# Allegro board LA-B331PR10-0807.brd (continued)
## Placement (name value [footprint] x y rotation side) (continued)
PQ52  -  [DMN65D8LW-7_SOT323-3]  266.36 19.08 0 bottom
PQ53  -  [DMN65D8LW-7_SOT323-3]  292.33 19.4 180 bottom
PQ54  -  [DMN65D8LW-7_SOT323-3]  288.76 17.35 0 bottom
PQ60  -  [DMN65D8LW-7_SOT323-3]  298.27 43.5 270 bottom
PQ61  -  [DMN65D8LW-7_SOT323-3]  298.66 39.02 180 bottom
PQ62  -  [DMN65D8LW-7_SOT323-3]  298.27 33.4 270 bottom
PQ101  FDV301N_G_NL_SOT23-3  [FDV301N_NL_SOT23-3]  298.16 12.12 90 bottom
PQ102  -  [MMST3904-7-F_SOT323-3]  300.97 18.2 270 bottom
PQ300  -  [CSD87330Q3D_SON8-7]  282.91 21.8 90 bottom
PQ501  -  [CSD87330Q3D_SON8-7]  277.61 22.59 270 bottom
PQ503  -  [AON7934_DFN3X3A8-10]  182.66 29.99 0 bottom
PQ600  -  [AON7934_DFN3X3A8-10]  215.98 19 0 bottom
PQ700  -  [CSD87312Q3E_SON8-4]  254.72 21.46 90 bottom
PQ701  -  [DCX124EK-7-F_SC74R-6]  250.77 22.75 270 bottom
PQ702  -  [CSD87351Q5D_SON8-7]  263.03 27.78 180 bottom
PQ703  -  [AON7405_DFN8-5]  258.05 46.64 270 bottom
PQ709  -  [DMN65D8LW-7_SOT323-3]  241.62 24.96 270 bottom
PQ720  -  [SI2303CDS-T1-GE3_SOT23-3]  245.51 22.42 0 bottom
PQ721  -  [DMN65D8LW-7_SOT323-3]  245.1 25.96 270 bottom
PQ900  -  [DMN66D0LDW-7_SOT363-6]  272.9 14.68 90 bottom
PQ901  -  [DMN66D0LDW-7_SOT363-6]  236.6 27.97 0 bottom
PR1  100_0402_1%  [R_0402]  242.15 40.99 0 bottom
PR2  100_0402_1%  [R_0402]  242.15 39.97 0 bottom
PR3  100K_0402_5%  [R_0402]  244.18 38.07 0 bottom
PR5  100_0402_1%  [R_0402]  244.18 38.96 0 bottom
PR7  402K_0402_1%  [R_0402]  246.24 41.85 90 bottom
PR8  324K_0402_1%  [R_0402]  249.29 42.77 270 bottom
PR9  324K_0402_1%  [R_0402]  242.15 41.9 0 bottom
PR10  240K_0402_5%  [R_0402]  244.21 42.77 270 bottom
PR12  402K_0402_1%  [R_0402]  274.5 18.08 90 bottom
PR13  100K_0402_5%  [R_0402]  242.3 27.78 180 bottom
PR30  100K_0402_5%  [R_0402]  239.69 23.87 270 bottom
PR40  100K_0402_5%  [R_0402]  240.26 41.91 180 bottom
PR41  9.1K_0402_1%  [R_0402]  240.27 42.82 180 bottom
PR42  100K_0402_1%  [R_0402]  236.64 33.19 180 bottom
PR43  0_0402_5%  [R_0402]  254.16 40.92 90 bottom
PR44  20K_0402_1%  [R_0402]  255.14 40.92 90 bottom
PR45  20K_0402_1%  [R_0402]  255.03 42.84 180 bottom
PR46  0_0402_5%  [R_0402]  225.78 33.8 180 bottom
PR48  0_0402_5%  [R0402_0OHM]  294.52 20.23 180 bottom
PR49  0_0402_5%  [R_0402]  254.14 39.86 0 bottom
PR55  0_0402_5%  [R_0402]  240.59 23.88 270 bottom
PR56  0_0402_5%  [R0402_0OHM]  239.69 21.2 90 bottom
PR58  100K_0402_5%  [R_0402]  250.26 41.88 90 bottom
PR59  0_0402_5%  [R0402_0OHM]  230.8 32.66 180 bottom
PR60  20K_0402_1%  [R_0402]  294.3 16.22 180 bottom
PR61  1M_0402_5%  [R_0402]  289.41 15.21 90 bottom
PR62  0_0402_5%  [R_0402]  268.06 19.52 0 bottom
PR63  1M_0402_5%  [R_0402]  268.59 18.51 180 bottom
PR65  1M_0402_5%  [R_0402]  288.34 15.27 90 bottom
PR67  0_0402_5%  [R_0402]  230.81 33.54 180 bottom
PR70  100K_0402_5%  [R_0402]  297.9 41.32 270 bottom
PR71  100K_0402_5%  [R_0402]  299.17 40.4 90 bottom
PR72  330K_0402_1%  [R_0402]  299.04 31.45 270 bottom
PR73  249K_0402_1%  [R_0402]  297.86 21.35 90 bottom
PR74  100K_0402_5%  [R_0402]  297.66 35.7 270 bottom
PR75  100K_0402_1%  [R_0402]  300.18 30.53 90 bottom
PR76  210K_0402_1%  [R_0402]  298.81 22.26 270 bottom
PR77  0_0402_5%  [R_0402]  248.14 40.42 180 bottom
PR78  0_0402_5%  [R0402_0OHM]  300.44 41.32 270 bottom
PR79  0_0402_5%  [R0402_0OHM]  294.42 18.45 90 bottom
PR80  560K_0402_1%  [R_0402]  299.22 29.4 180 bottom
PR81  100K_0402_5%  [R_0402]  298.89 35.73 0 bottom
PR93  0_0402_5%  [R0402_0OHM]  268.97 20.41 180 bottom
PR94  1M_0402_5%  [R_0402]  241.77 33.88 0 bottom
PR95  0_0402_5%  [R0402_0OHM]  273.62 18.08 90 bottom
PR102  2.2K_0402_5%  [R_0402]  299.07 16.01 0 bottom
PR103  33_0402_5%  [R_0402]  299.41 14.72 0 bottom
PR104  10K_0402_1%  [R_0402]  300.48 19.96 180 bottom
PR105  100K_0402_1%  [R_0402]  297.88 16.03 90 bottom
PR106  15K_0402_1%  [R_0402]  297.88 17.9 90 bottom
PR130  0_0402_5%  [R_0402]  297.55 14.72 0 bottom
PR300  66.5K_0402_1%  [R_0402]  282.43 34.13 180 bottom
PR301  154K_0402_1%  [R_0402]  279.39 34.13 180 bottom
PR302  100K_0402_1%  [R_0402]  282.43 33.24 180 bottom
PR303  100K_0402_1%  [R_0402]  279.37 33.2 180 bottom
PR304  7.68K_0402_1%  [R_0402]  283.37 34.14 270 bottom
PR305  5.49K_0402_1%  [R_0402]  277.56 34.1 270 bottom
PR306  200_0402_1%  [R_0402]  277.1 31.08 180 bottom
PR307  0_0603_5%  [R_0603]  285.53 29.62 180 bottom
PR308  0_0603_5%  [R_0603]  276.9 28.99 180 bottom
PR309  4.7_0805_5%  [R_0805]  284.77 25.34 90 bottom
PR310  4.7_0805_5%  [R_0805]  276.01 24.77 90 bottom
PR311  100K_0402_1%  [R_0402]  281.16 35.91 180 bottom
PR330  0_0402_5%  [R0402_0OHM]  284.31 33.11 0 bottom
PR331  0_0402_5%  [R0402_0OHM]  277.1 32.1 180 bottom
PR400  0_0402_5%  [R0402_0OHM]  286.45 45.22 0 bottom
PR401  88.7K_0402_1%  [R_0402]  283.95 41.6 0 bottom
PR402  4.7_0805_5%  [R_0805]  291.04 38.9 0 bottom
PR403  100K_0402_1%  [R_0402]  283.93 42.54 0 bottom
PR404  100K_0402_5%  [R_0402]  285.75 39.39 180 bottom
PR405  0_0402_5%  [R0402_0OHM]  274.26 45.48 0 bottom
PR406  412K_0402_1%  [R_0402]  271.61 41.75 0 bottom
PR407  4.7_0805_5%  [R_0805]  278.84 39.15 0 bottom
PR408  324K_0402_1%  [R_0402]  271.61 42.77 0 bottom
PR409  100K_0402_5%  [R_0402]  273.55 39.64 180 bottom
PR500  0_0402_5%  [R0402_0OHM]  73.26 29.66 180 bottom
PR501  1M_0402_1%  [R_0402]  73.26 28.78 180 bottom
PR502  4.7_1206_5%  [R_1206]  81.88 29.47 270 bottom
PR503  0_0603_5%  [R_0603]  74.39 20.65 180 bottom
PR504  0_0402_5%  [R_0402]  72.34 25.6 0 bottom
PR505  21K_0402_1%  [R_0402]  72.68 23.87 270 bottom
PR506  100K_0402_5%  [R_0402]  72.34 27 0 bottom
PR507  0_0402_5%  [R0402_0OHM]  73.26 24.71 180 bottom
PR508  35.7K_0402_1%  [R_0402]  71.66 22.85 90 bottom
PR509  75_0402_1%  [R_0402]  193.28 16.86 180 bottom
PR510  130_0402_1%  [R_0402]  190.33 18.89 0 bottom
PR511  0_0402_5%  [R0402_0OHM]  187.49 15.28 270 bottom
PR512  1.91K_0402_1%  [R_0402]  190.16 15.28 270 bottom
PR513  54.9_0402_1%  [R_0402]  190.33 17.01 0 bottom
PR514  73.2K_0402_1%  [R_0402]  190.33 20.16 0 bottom
PR515  0_0402_5%  [R0402_0OHM]  193.28 18.89 180 bottom
PR516  0_0402_5%  [R0402_0OHM]  193.28 17.87 180 bottom
PR517  0_0402_5%  [R0402_0OHM]  193.28 15.84 180 bottom
PR518  124K_0402_1%  [R_0402]  185.9 23.06 90 bottom
PR519  0_0402_5%  [R0402_0OHM]  191.04 14.37 90 bottom
PR520  105K_0402_1%  [R_0402]  189.27 14.37 90 bottom
PR521  127K_0402_1%  [R_0402]  71.67 21.73 270 bottom
PR526  3.83K_0402_1%  [R_0402]  186.47 15.28 270 bottom
PR529  27.4K_0402_1%  [R_0402]  186.47 13.25 270 bottom
PR530  100K_0402_5%  [R_0402]  77.9 15.18 0 bottom
PR538  2.2_0603_5%  [R_0603]  188.06 24.02 270 bottom
PR540  732_0402_1%  [R_0402]  182.74 18 180 bottom
PR542  10_0402_1%  [R_0402]  180.58 14.98 270 bottom
PR546  3.65K_0603_1%  [R_0603]  181.07 20.92 0 bottom
PR548  4.7_1206_5%  [R_1206]  182.73 25.37 0 bottom
PR550  909_0402_1%  [R_0402]  181.43 15.04 0 bottom
PR560  0_1206_5%  [R_1206]  194.82 31.89 0 bottom
PR561  0_1206_5%  [R_1206]  194.82 29.84 0 bottom
PR562  4.99M_0402_1%  [R_0402]  184.11 22.06 0 bottom
PR563  2.61K_0402_1%  [R_0402]  183.25 22.06 180 bottom
PR564  3.65K_0402_1%  [R_0402]  185.46 14.37 90 bottom
PR565  11K_0402_1%  [R_0402]  182.78 19.82 270 bottom
PR600  2.2_0603_5%  [R_0603]  215.62 24.92 90 bottom
PR601  3.57K_0402_1%  [R_0402]  218.98 22.24 90 bottom
PR602  4.7_1206_5%  [R_1206]  214.86 13.56 0 bottom
PR603  5.1_0603_5%  [R_0603]  222.79 21.75 90 bottom
PR604  100K_0402_5%  [R_0402]  223.76 24.22 180 bottom
PR605  8.06K_0402_1%  [R_0402]  222.49 30.32 180 bottom
PR606  887K_0402_1%  [R_0402]  223.76 25.24 180 bottom
PR607  10K_0402_1%  [R_0402]  222.49 31.34 180 bottom
PR608  0_0402_5%  [R0402_0OHM]  222.84 26.26 0 bottom
PR609  0_0402_5%  [R0402_0OHM]  222.84 29.3 0 bottom
PR700  0.01_1206_1%  [R_1206_4P-D]  264.32 19.86 180 bottom
PR701  4.7_0402_1%  [R_0402]  252.96 23.14 90 bottom
PR702  4.02K_0402_1%  [R_0402]  251.89 24.06 270 bottom
PR703  0_0402_5%  [R0402_0OHM]  250.76 28.22 270 bottom
PR704  0_0402_5%  [R0402_0OHM]  251.62 27.54 0 bottom
PR705  10_1206_5%  [R_1206]  256.32 29.75 90 bottom
PR706  4.02K_0402_1%  [R_0402]  256.22 25.47 180 bottom
PR707  294K_0402_1%  [R_0402]  246.67 28.34 90 bottom
PR708  2.2_0603_5%  [R_0603]  253.34 33.62 0 bottom
PR709  49.9K_0402_1%  [R_0402]  248.65 28.29 180 bottom
PR710  100K_0402_1%  [R_0402]  242.99 26.74 0 bottom
PR711  0_0402_5%  [R0402_0OHM]  243.93 27.78 0 bottom
PR712  150K_0402_1%  [R_0402]  244.84 28.8 180 bottom
PR713  0_0402_5%  [R0402_0OHM]  241.39 29.81 0 bottom
PR714  0_0402_5%  [R0402_0OHM]  241.39 32.86 0 bottom
PR715  0_0402_5%  [R0402_0OHM]  241.39 30.83 0 bottom
PR716  0_0402_5%  [R0402_0OHM]  241.39 31.84 0 bottom
PR717  0.01_1206_1%  [R_1206_4P-D]  266.62 45.02 270 bottom
PR718  4.02K_0402_1%  [R_0402]  249.59 36.97 90 bottom
PR719  4.7_1206_5%  [R_1206]  266.38 33.71 90 bottom
PR720  1K_0603_1%  [R_0603]  247.18 36.99 90 bottom
PR721  1K_0402_5%  [R_0402]  253.22 36.92 180 bottom
PR722  0_0402_5%  [R0402_0OHM]  246.04 37.89 270 bottom
PR723  121K_0402_1%  [R_0402]  252.26 37.86 90 bottom
PR730  0_0402_5%  [R0402_0OHM]  243.93 32.86 0 bottom
PR731  0_0402_5%  [R0402_0OHM]  243.93 33.88 0 bottom
PR740  10K_0402_1%  [R_0402]  254.23 37.89 270 bottom
PR745  49.9K_0402_1%  [R_0402]  241.54 34.97 0 bottom
PR770  20K_0402_1%  [R_0402]  255.41 37.9 270 bottom
PR771  499K_0402_1%  [R_0402]  246.86 18.44 180 bottom
PR772  499K_0402_1%  [R_0402]  244.87 18.43 180 bottom
PR773  100K_0402_5%  [R_0402]  248.12 20.37 90 bottom
PR774  0_0402_5%  [R_0402]  246.11 24.17 0 bottom
PR900  232K_0402_1%  [R_0402]  271.81 13.3 90 bottom
PR901  1.91K_0402_1%  [R_0402]  273.09 12.59 90 bottom
PR902  2M_0402_5%  [R_0402]  271.81 15.28 90 bottom
PR903  10K_0402_1%  [R_0402]  267.68 17.62 0 bottom
PR904  10K_0402_1%  [R_0402]  281.47 16.4 90 bottom
PR905  84.5K_0402_1%  [R_0402]  269.83 13.05 0 bottom
PR906  22.6K_0402_1%  [R_0402]  285.84 12.56 180 bottom
PR907  232K_0402_1%  [R_0402]  264.91 12.79 180 bottom
PR908  48.7K_0402_1%  [R_0402]  270.75 15.33 180 bottom
PR909  2M_0402_5%  [R_0402]  261.71 15.08 0 bottom
PR910  10K_0402_1%  [R_0402]  262.62 16.1 180 bottom
PR911  84.5K_0402_1%  [R_0402]  262.62 12.79 180 bottom
PR912  42.2K_0402_1%  [R_0402]  269.83 16.22 0 bottom
PR913  0_0402_5%  [R_0402]  77.9 14.23 0 bottom
PU300  -  [TPS51285BRUKR_QFN20_3X3]  279.69 31.59 0 bottom
PU400  -  [TLV62150RGTR_QFN16_3X3]  288.63 40.81 180 bottom
PU401  -  [TLV62150RGTR_QFN16_3X3]  276.44 41.06 180 bottom
PU500  -  [SY8206DQNC_QFN10_3X3]  75.83 23.87 270 bottom
PU600  -  [G5616ARZ1U_TQFN20_3X3]  218.44 28.25 0 bottom
PU700  BQ24777RUYR_WQFN28_4x4  [BQ24777RUYR_WQFN28_4X4]  250.41 31.06 90 bottom
PU702  -  [ISL95813HRZ-T_QFN20_3X4]  187.81 17.3 180 bottom
PU900  -  [LM393DMR2G_MICRO8]  268.35 16.06 270 bottom
PU901  -  [M74VHC1GT00DFT2G_SC70-5]  282.82 18.81 0 bottom
PU902  -  [M74VHC1GT00DFT2G_SC70-5]  284.12 13.67 180 bottom
PU904  -  [LM393DMR2G_MICRO8]  298.1 27.85 0 bottom
Q1  -  [DMN66D0LDW-7_SOT363-6]  117.53 25.05 180 bottom
Q2  SI3457CDV-T1-GE3_TSOP6  [SI3457BDV-T1-E3_TSOP6]  243.1 11.58 180 bottom
Q3  DII-DMN65D8LW-7  [SSM3K7002FU_SC70-3]  239.24 10.25 270 bottom
Q4  DII-DMN65D8LW-7  [SSM3K7002FU_SC70-3]  242.35 8.16 0 bottom
Q5  DII-DMN65D8LW-7  [SSM3K7002FU_SC70-3]  306.36 93.12 180 bottom
Q7  DII-DMN65D8LW-7  [SSM3K7002FU_SC70-3]  51.47 4.73 180 bottom
Q11  SiSA12DN-T1-GE3_POWERPAK8-5  [SIS412DN-T1-GE3_POWERPAK8-5]  86.82 28.26 270 bottom
Q12  -  [SI1553CDL-T1-GE3_SC70-6]  91.59 26.39 0 bottom
Q13  DII-DMN65D8LW-7  [SSM3K7002FU_SC70-3]  95.79 26.83 180 bottom
Q14  DII-DMN65D8LW-7  [SSM3K7002FU_SC70-3]  92.24 29.75 0 bottom
Q15  SiSA12DN-T1-GE3_POWERPAK8-5  [SIS412DN-T1-GE3_POWERPAK8-5]  86.82 23.69 270 bottom
Q16  -  [SI1553CDL-T1-GE3_SC70-6]  90.34 20.05 270 bottom
Q17  DII-DMN65D8LW-7  [SSM3K7002FU_SC70-3]  89 15.84 90 bottom
Q18  DII-DMN65D8LW-7  [SSM3K7002FU_SC70-3]  92.24 23.27 0 bottom
Q19  SiSA12DN-T1-GE3_POWERPAK8-5  [SIS412DN-T1-GE3_POWERPAK8-5]  86.12 16.44 180 bottom
Q20  -  [SI1553CDL-T1-GE3_SC70-6]  83.98 10.11 90 bottom
Q21  DII-DMN65D8LW-7  [SSM3K7002FU_SC70-3]  89 10.76 90 bottom
Q22  DII-DMN65D8LW-7  [SSM3K7002FU_SC70-3]  89 13.3 90 bottom
Q23  DII-DMN65D8LW-7  [SSM3K7002FU_SC70-3]  284.84 76.04 90 bottom
Q24  -  [MMBT3904WH_SOT323-3]  161.87 18.6 270 bottom
Q25  -  [MMBT3904WH_SOT323-3]  245.01 54.02 180 bottom
Q26  -  [MMBT3904WH_SOT323-3]  294.93 74.31 180 bottom
Q27  -  [MMBT3904WH_SOT323-3]  34.47 25.24 270 bottom
Q29  -  [MMBT3904WH_SOT323-3]  137.23 57.43 90 bottom
Q41  -  [DMN66D0LDW-7_SOT363-6]  302.62 93.42 90 bottom
Q43  DII-DMN65D8LW-7  [SSM3K7002FU_SC70-3]  53.88 4.73 180 bottom
Q44  -  [DMN66D0LDW-7_SOT363-6]  291.07 70.98 270 bottom
Q45  -  [DMN66D0LDW-7_SOT363-6]  300.67 74.77 270 bottom
Q46  DII-DMN65D8LW-7  [SSM3K7002FU_SC70-3]  41.1 12.06 180 bottom
Q47  -  [DMN66D0LDW-7_SOT363-6]  5.07 41.43 90 bottom
Q48  DII-DMN65D8LW-7  [SSM3K7002FU_SC70-3]  60.92 6.8 0 bottom
QH1  -  [DMN66D0LDW-7_SOT363-6]  103.99 20.53 90 bottom
QV1  -  [BSS138-G_SOT23-3]  20.64 38.45 270 bottom
R1  1M_0402_5%  [R_0402]  116.83 23.97 180 bottom
R2  3K_0402_5%  [R_0402]  111.85 22.95 0 bottom
R6  1K_0402_5%  [R_0402]  161.78 3.4 180 bottom
R7  1.5K_0402_5%  [R_0402]  161.78 4.41 180 bottom
R8  150_0402_5%  [R_0402]  166.86 9.24 180 bottom
R9  0_1206_5%  [R_1206]  134.69 2.99 180 bottom
R10  0_1206_5%  [R1206_0OHM]  128.03 2.99 0 bottom
R11  0_1206_5%  [R1206_0OHM]  136.18 5.32 180 bottom
R12  10K_0402_5%  [R_0402]  180.38 6.14 270 bottom
R13  10K_0402_5%  [R_0402]  179.56 2.89 180 bottom
R14  3K_0402_5%  [R_0402]  194.09 3.45 90 bottom
R15  1K_0402_5%  [R_0402]  170.27 29.43 0 bottom
R16  0_0402_5%  [R_0402]  195.11 4.36 270 bottom
R17  1K_0402_5%  [R_0402]  196.59 6.9 270 bottom
R19  0_0805_5%  [R0805_0OHM]  253.95 18.13 0 bottom
R20  0_0402_5%  [R_0402]  196.63 54.15 270 bottom
R22  0_0402_5%  [R_0402]  197.65 54.15 270 bottom
R23  220K_0402_5%  [R_0402]  248.09 18.2 90 bottom
R25  0_0603_5%  [R_0603]  241.15 15.84 0 bottom
R28  1M_0402_5%  [R_0402]  238.54 13 270 bottom
R32  220K_0402_5%  [R_0402]  238.03 4.87 270 bottom
R33  100K_0402_5%  [R_0402]  237.53 13 270 bottom
R35  100K_0402_5%  [R_0402]  308.13 90.82 90 bottom
R39  820_0805_1%  [R_0805]  243.2 9.75 180 bottom
R40  100K_0402_5%  [R_0402]  307.25 91.74 270 bottom
R41  0_0402_5%  [R_0402]  306.36 91.74 270 bottom
R44  220K_0402_5%  [R_0402]  257.01 17.11 0 bottom
R48  220K_0402_5%  [R_0402]  259.55 17.11 0 bottom
R52  0_0402_5%  [R0402_0OHM]  197.9 34.94 90 bottom
R54  0_0402_5%  [R0402_0OHM]  198.92 34.94 90 bottom
R55  0_0402_5%  [R0402_0OHM]  195.62 39.26 90 bottom
R60  0_0402_5%  [R0402_0OHM]  28.84 33.36 270 bottom
R61  0_0402_5%  [R0402_0OHM]  21.12 31.89 90 bottom
R62  0_0402_5%  [R0402_0OHM]  27.82 33.36 270 bottom
R63  0_0402_5%  [R0402_0OHM]  20.1 31.89 90 bottom
R64  0_0402_5%  [R0402_0OHM]  19.09 31.89 90 bottom
R65  0_0402_5%  [R0402_0OHM]  17.13 32.63 0 bottom
R68  220K_0402_5%  [R_0402]  17.82 34.18 90 bottom
R69  0_0402_5%  [R0402_0OHM]  47.03 5.22 90 bottom
R70  100K_0402_5%  [R_0402]  57.69 5.73 90 bottom
R71  0_0402_5%  [R0402_0OHM]  48.04 5.22 90 bottom
R72  47K_0402_5%  [R_0402]  50.84 2.47 180 bottom
R73  10K_0402_5%  [R_0402]  51.71 2.43 90 bottom
R76  0_0402_5%  [R0402_0OHM]  29.7 46.69 180 bottom
R78  0_1206_5%  [R1206_0OHM]  31.53 45.12 90 bottom
R79  100K_0402_5%  [R_0402]  31.02 38.24 90 bottom
R138  0_0402_5%  [R_0402]  198.66 54.15 270 bottom
R139  0_0402_5%  [R_0402]  199.68 54.15 270 bottom
R142  0_0402_5%  [R0402_0OHM]  225.38 29.94 0 bottom
R143  0_0603_5%  [R0603_0OHM]  232 28.29 0 bottom
R146  0_1206_5%  [R1206_0OHM]  35.6 45.24 90 bottom
R147  100K_0402_5%  [R_0402]  35.6 37.99 90 bottom
R148  100K_0402_5%  [R_0402]  79.23 46.32 180 bottom
R149  0_0402_5%  [R0402_0OHM]  79.23 45.31 180 bottom
R151  0_0603_5%  [R0603_0OHM]  4.95 39.16 0 bottom
R152  0_0402_5%  [R0402_0OHM]  236.56 18.89 0 bottom
R153  0_0603_5%  [R0603_0OHM]  296.84 63.53 90 bottom
R154  0_1206_5%  [R_1206]  86.08 31.08 0 bottom
R155  100K_0402_5%  [R_0402]  298.11 57.29 90 bottom
R156  0_0402_5%  [R0402_0OHM]  84.36 37.48 90 bottom
R157  0_0402_5%  [R0402_0OHM]  85.38 37.48 90 bottom
R158  100K_0402_5%  [R_0402]  299.12 57.29 90 bottom
R159  0_0603_5%  [R0603_0OHM]  300.39 63.53 90 bottom
R160  0_0603_5%  [R0603_0OHM]  232 31.72 0 bottom
R161  0_0603_5%  [R0603_0OHM]  240.19 17.3 0 bottom
R162  100K_0402_5%  [R_0402]  225.38 30.95 0 bottom
R163  100K_0402_5%  [R_0402]  236.54 19.83 0 bottom
R167  470_0402_5%  [R_0402]  88.73 29.56 0 bottom
R168  100K_0402_5%  [R_0402]  96.25 30.07 180 bottom
R169  10K_0402_5%  [R_0402]  94.02 25.04 90 bottom
R170  330_0402_5%  [R_0402]  89.65 26.38 180 bottom
R171  330_0402_5%  [R_0402]  89.65 25.49 180 bottom
R172  0_0402_5%  [R0402_0OHM]  96.25 31.08 180 bottom
R173  100K_0402_5%  [R_0402]  95.34 32.1 0 bottom
R174  470_0402_5%  [R_0402]  88.86 24.48 0 bottom
R175  100K_0402_5%  [R_0402]  93.2 15.08 180 bottom
R176  10K_0402_5%  [R_0402]  88.99 17.62 0 bottom
R177  330_0402_5%  [R_0402]  89.9 22.19 180 bottom
R178  0_0402_5%  [R0402_0OHM]  96.81 13.61 90 bottom
R179  330_0402_5%  [R_0402]  89.9 21.18 180 bottom
R180  0_0402_5%  [R_0402]  93.2 14.06 180 bottom
R181  100K_0402_5%  [R_0402]  92.24 16.15 90 bottom
R182  470_0402_5%  [R_0402]  87.67 15.03 270 bottom
R183  100K_0402_5%  [R_0402]  93.2 12.03 180 bottom
R184  10K_0402_5%  [R_0402]  86.9 11.47 270 bottom
R185  330_0402_5%  [R_0402]  83.91 12.54 0 bottom
R186  0_0402_5%  [R0402_0OHM]  87.79 13 270 bottom
R187  330_0402_5%  [R_0402]  86.6 12.54 180 bottom
R188  0_0402_5%  [R_0402]  93.2 13.05 180 bottom
R189  100K_0402_5%  [R_0402]  92.29 11.02 0 bottom
R190  0_0603_5%  [R0603_0OHM]  15.34 36.54 0 bottom
R191  0_0603_5%  [R0603_0OHM]  14.08 43.56 0 bottom
R192  100K_0402_5%  [R_0402]  8.15 41.89 270 bottom
R193  0_0603_5%  [R0603_0OHM]  15.34 39.84 0 bottom
R194  100K_0402_5%  [R_0402]  8.21 37.43 0 bottom
R195  1K_0402_5%  [R_0402]  8.21 38.45 0 bottom
R201  10K_0402_5%  [R_0402]  189.77 4.36 270 bottom
R202  0_0402_5%  [R0402_0OHM]  185.2 3.45 90 bottom
R206  0_0603_5%  [R0603_0OHM]  300.45 77.82 180 bottom
R207  4.3K_0402_5%  [R_0402]  298.44 81.63 180 bottom
R208  0_0402_5%  [R0402_0OHM]  292.39 87.42 270 bottom
R210  SHORT PADS  [SHORTPADS]  289.85 89.76 90 bottom
R212  10K_0402_5%  [R_0402]  299.5 83.61 270 bottom
R213  0_0402_5%  [R0402_0OHM]  300.52 82.69 90 bottom
R214  100K_0402_5%  [R_0402]  284.95 87.6 0 bottom
R215  100K_0402_5%  [R_0402]  288.78 77.06 180 bottom
R219  43_0402_5%  [R_0402]  286.8 86.5 90 bottom
R222  0_0402_5%  [R0402_0OHM]  298.49 82.69 90 bottom
R223  10K_0402_5%  [R_0402]  298.36 91.1 270 bottom
R225  100K_0402_5%  [R_0402]  285.53 73.04 90 bottom
R227  0_0402_5%  [R_0402]  297.47 82.69 90 bottom
R228  4.7K_0402_5%  [R_0402]  294.96 76.71 270 bottom
R229  100K_0402_5%  [R_0402]  289.85 87.42 270 bottom
R230  1.5K_0402_1%  [R_0402]  283.45 85.18 180 bottom
R231  10_0402_1%  [R_0402]  290.52 77.07 270 bottom
R233  8.2K_0402_5%  [R_0402]  296.71 73.8 90 bottom
R234  49.9_0402_1%  [R_0402]  293.28 92.35 90 bottom
R235  2.2K_0402_5%  [R_0402]  296.71 72.94 270 bottom
R236  10K_0402_5%  [R_0402]  297.34 92.22 90 bottom
R237  10K_0402_5%  [R_0402]  298.36 92.22 90 bottom
R239  100K_0402_5%  [R_0402]  297.34 90.19 90 bottom
R240  0_0402_5%  [R0402_0OHM]  295.44 82.69 90 bottom
R241  0_0402_5%  [R0402_0OHM]  296.45 82.69 90 bottom
R243  10K_0402_5%  [R_0402]  284.82 80.1 0 bottom
R244  10K_0402_5%  [R_0402]  285.74 79.09 180 bottom
R284  47K_0402_5%  [R_0402]  5.04 37.94 0 bottom
R290  10K_0402_5%  [R_0402]  53.88 2.43 90 bottom
R291  0_0603_5%  [R0603_0OHM]  72.87 48.35 180 bottom
R292  0_0603_5%  [R0603_0OHM]  74.78 44.8 0 bottom
R300  0_0402_5%  [R0402_0OHM]  196.68 41.5 0 bottom
R301  0_0402_5%  [R0402_0OHM]  198.71 41.5 0 bottom
R303  100K_0402_5%  [R_0402]  7.73 33.88 180 bottom
R306  100K_0402_5%  [R_0402]  79.23 48.35 180 bottom
R307  0_0603_5%  [R0603_0OHM]  298.61 48.29 270 bottom
R308  100K_0402_5%  [R_0402]  299.12 54.91 270 bottom
R309  10K_0402_5%  [R_0402]  284.82 78.07 0 bottom
R310  1K_0402_5%  [R_0402]  166.74 15.59 180 bottom
R316  4.7K_0402_5%  [R_0402]  73.01 10.43 90 bottom
R317  4.7K_0402_5%  [R_0402]  76.52 10.43 90 bottom
R318  4.7K_0402_5%  [R_0402]  74.76 10.43 90 bottom
R319  4.7K_0402_5%  [R_0402]  72.13 10.43 90 bottom
R320  4.99K_0402_1%  [R_0402]  76.44 18.16 180 bottom
R321  0_0603_5%  [R0603_0OHM]  80.35 11.49 270 bottom
R322  100K_0402_5%  [R_0402]  80.35 16.6 0 bottom
R323  0_0402_5%  [R0402_0OHM]  79.23 47.34 180 bottom
R324  10K_0402_5%  [R_0402]  285.06 90.15 180 bottom
R326  220K_0402_5%  [R_0402]  18.71 34.18 90 bottom
R327  10K_0402_5%  [R_0402]  52.74 2.43 90 bottom
R328  0_0402_5%  [R_0402]  287.07 70.97 0 bottom
R329  0_0402_5%  [R0402_0OHM]  287.07 70.1 0 bottom
R330  10K_0402_5%  [R_0402]  297.72 72.94 270 bottom
R331  2.2K_0402_5%  [R_0402]  290.18 68.42 180 bottom
R332  2.2K_0402_5%  [R_0402]  291.17 68.42 0 bottom
R333  549K_0402_1%  [R_0402]  300.21 75.79 180 bottom
R334  100K_0402_1%  [R_0402]  299.3 76.67 0 bottom
R335  0.01_0603_1%  [R_0603]  300.26 56.39 270 bottom
R336  0.01_0603_1%  [R_0603]  294.04 63.4 90 bottom
R337  100K_0402_5%  [R_0402]  308.39 92.85 90 bottom
R338  0_0402_5%  [R_0402]  301.58 95.72 0 bottom
R339  0_0402_5%  [R_0402]  301.53 94.79 270 bottom
R340  10K_0402_5%  [R_0402]  287.87 75.28 0 bottom
R341  100K_0402_5%  [R_0402]  289.61 75.28 0 bottom
R342  0_0402_5%  [R_0402]  73.16 40.8 0 bottom
R343  0_0402_5%  [R_0402]  73.26 30.57 180 bottom
R344  0_1206_5%  [R_1206]  88.73 33.05 0 bottom
R345  0_0603_5%  [R0603_0OHM]  243.03 21.48 180 bottom
R346  0_0603_5%  [R_0603]  241.65 22.86 0 bottom
R348  0_0402_5%  [R_0402]  41.85 10.78 180 bottom
R349  10K_0402_5%  [R_0402]  297.28 78.1 90 bottom
R350  100K_0402_5%  [R_0402]  284.65 73.05 90 bottom
R351  0_0402_5%  [R0402_0OHM]  292.05 70.14 90 bottom
R352  0_0402_5%  [R0402_0OHM]  290.67 67.44 0 bottom
R353  0_0402_5%  [R_0402]  300.48 72.37 180 bottom
R354  10K_0402_5%  [R_0402]  300.99 68.48 90 bottom
R356  2.2K_0402_5%  [R_0402]  282.75 86.8 0 bottom
R357  0_0402_5%  [R0402_0OHM]  291.41 75.66 90 bottom
R358  0_0402_5%  [R_0402]  49.85 6.75 90 bottom
R360  0.01_0603_1%  [R_0603]  78.85 40.41 0 bottom
R361  100K_0402_5%  [R_0402]  73.16 41.7 0 bottom
R362  0_0402_5%  [R_0402]  57.61 4.28 0 bottom
R363  0_0402_5%  [R_0402]  57.61 3.38 0 bottom
R364  0_0402_5%  [R_0402]  57.61 2.51 0 bottom
R365  0_0402_5%  [R0402_0OHM]  6.26 40.43 0 bottom
R366  0_0402_5%  [R_0402]  61.47 2.77 180 bottom
R367  0_0402_5%  [R_0402]  61.47 3.66 180 bottom
R368  0_0402_5%  [R_0402]  73.17 39.91 270 bottom
R369  0_0402_5%  [R_0402]  87.36 38.4 270 bottom
R370  0_1206_5%  [R1206_0OHM]  81.21 39.15 270 bottom
R371  0_0402_5%  [R_0402]  300.09 54.06 270 bottom
R379  4.7K_0402_5%  [R_0402]  73.89 10.43 90 bottom
R380  4.7K_0402_5%  [R_0402]  77.39 10.43 90 bottom
R381  4.7K_0402_5%  [R_0402]  75.64 10.43 90 bottom
R382  0_0402_5%  [R_0402]  71.26 10.43 90 bottom
R383  0_0402_5%  [R_0402]  74.7 18.16 180 bottom
R384  0_0402_5%  [R_0402]  299.74 45.37 90 bottom
R385  0_0402_5%  [R0402_0OHM]  298.24 54.91 270 bottom
R386  0_0402_5%  [R_0402]  50 3.34 90 bottom
R387  0_0402_5%  [R_0402]  278.51 50.3 0 bottom
R388  0_0402_5%  [R_0402]  301.74 85.84 90 bottom
R389  0_0402_5%  [R_0402]  49.06 3.38 270 bottom
R390  0_0402_5%  [R_0402]  62.71 3.66 90 bottom
R391  0_0402_5%  [R_0402]  62.71 6.34 270 bottom
RC1  24.9_0402_1%  [R_0402]  139.02 7.97 0 bottom
RC2  0_0402_5%  [R_0402]  107.58 18.94 0 bottom
RC4  100K_0402_5%  [R_0402]  94.07 11.52 0 bottom
RC6  62_0402_5%  [R_0402]  169 9.49 0 bottom
RC8  56_0402_5%  [R_0402]  166.86 8.22 180 bottom
RC10  10K_0402_5%  [R_0402]  164.07 5.43 180 bottom
RC11  51_0402_5%  [R_0402]  169 7.21 0 bottom
RC12  200_0402_1%  [R_0402]  160.79 29.35 90 bottom
RC13  121_0402_1%  [R_0402]  159.78 29.35 90 bottom
RC14  100_0402_1%  [R_0402]  158.76 29.35 90 bottom
RC15  51_0402_5%  [R_0402]  169.15 5.17 0 bottom
RC16  51_0402_5%  [R_0402]  169.15 6.19 0 bottom
RC17  220K_0402_5%  [R_0402]  146.34 35.33 270 bottom
RC18  2M_0402_5%  [R_0402]  147.36 34.42 90 bottom
RC19  470_0402_5%  [R_0402]  137.7 27.56 90 bottom
RC20  0_0402_5%  [R0402_0OHM]  136.69 27.56 90 bottom
RC21  1K_0402_5%  [R_0402]  163.15 6.44 0 bottom
RC22  49.9_0402_1%  [R_0402]  133.13 27.81 90 bottom
RC23  0_0402_5%  [R0402_0OHM]  160.87 6.44 0 bottom
RC24  100_0402_1%  [R_0402]  166.86 4.16 180 bottom
RC25  0_0402_5%  [R0402_0OHM]  166.81 5.17 180 bottom
RC26  43_0402_5%  [R_0402]  156.5 4.72 90 bottom
RC27  0_0402_5%  [R0402_0OHM]  155.48 4.72 90 bottom
RC28  0_0402_5%  [R0402_0OHM]  158.48 4.67 180 bottom
RC29  0_0402_5%  [R0402_0OHM]  170.27 28.41 0 bottom
RC30  0_0402_5%  [R0402_0OHM]  164.07 4.41 180 bottom
RC31  0_0402_5%  [R0402_0OHM]  161.78 5.43 180 bottom
RC32  75_0402_5%  [R_0402]  156.5 3.85 270 bottom
RC33  130_0402_1%  [R_0402]  157.57 2.89 90 bottom
RC34  1K_0402_5%  [R_0402]  164.88 15.13 90 bottom
RC35  49.9_0402_1%  [R_0402]  162.16 14.04 90 bottom
RC36  49.9_0402_1%  [R_0402]  124.24 28.59 90 bottom
RC37  8.2K_0402_1%  [R_0402]  122.21 12.54 180 bottom
RC38  0_0402_5%  [R0402_0OHM]  165.95 6.19 0 bottom
RC39  100_0402_1%  [R_0402]  165.95 7.21 0 bottom
RC40  0_0402_5%  [R0402_0OHM]  216.62 8.93 180 bottom
RC41  0_0402_5%  [R0402_0OHM]  215.12 7.97 180 bottom
RC42  0_0402_5%  [R0402_0OHM]  214.11 8.98 180 bottom
RC43  0_0402_5%  [R0402_0OHM]  213.09 7.97 180 bottom
RC44  0_0402_5%  [R0402_0OHM]  212.08 8.98 180 bottom
RC45  0_0402_5%  [R0402_0OHM]  210.81 7.97 180 bottom
RC46  0_0402_5%  [R0402_0OHM]  209.79 8.98 180 bottom
RC47  0_0402_5%  [R0402_0OHM]  207.6 7.97 0 bottom
RC49  0_0402_5%  [R0402_0OHM]  117.93 8.39 0 bottom
RC50  0_0402_5%  [R0402_0OHM]  113.14 10.53 270 bottom
RC51  10K_0402_5%  [R_0402]  128.15 6.05 90 bottom
RD1  240_0402_1%  [R_0402]  178.09 57.04 90 bottom
RD2  240_0402_1%  [R_0402]  190.54 57.04 90 bottom
RD3  240_0402_1%  [R_0402]  179.11 57.04 90 bottom
RD4  240_0402_1%  [R_0402]  191.55 57.04 90 bottom
RD5  240_0402_1%  [R_0402]  151.17 57.04 90 bottom
RD6  240_0402_1%  [R_0402]  161.07 57.04 90 bottom
RD7  240_0402_1%  [R_0402]  152.18 57.04 90 bottom
RD8  240_0402_1%  [R_0402]  162.09 57.04 90 bottom
RD9  240_0402_1%  [R_0402]  135.47 51.15 0 bottom
RD10  240_0402_1%  [R_0402]  122.21 57.04 90 bottom
RD11  240_0402_1%  [R_0402]  135.47 50.13 0 bottom
RD12  240_0402_1%  [R_0402]  123.23 57.04 90 bottom
RD13  240_0402_1%  [R_0402]  89.19 57.02 90 bottom
RD14  240_0402_1%  [R_0402]  100.37 57.04 90 bottom
RD15  240_0402_1%  [R_0402]  90.21 57.02 90 bottom
RD16  240_0402_1%  [R_0402]  102.14 57.04 90 bottom
RD17  1.8K_0402_1%  [R_0402]  86.14 57.04 90 bottom
RD18  2.7_0402_1%  [R_0402]  85.13 57.96 270 bottom
RD19  1.8K_0402_1%  [R_0402]  87.16 57.04 90 bottom
RD20  24.9_0402_1%  [R_0402]  83.09 57.04 90 bottom
RD21  1.8K_0402_1%  [R_0402]  141.62 57.96 270 bottom
RD22  1.8K_0402_1%  [R_0402]  128.31 57.96 270 bottom
RD23  4.99_0402_1%  [R_0402]  142.63 57.96 270 bottom
RD24  4.99_0402_1%  [R_0402]  126.27 57.96 270 bottom
RD25  1.8K_0402_1%  [R_0402]  140.6 57.04 90 bottom
RD26  1.8K_0402_1%  [R_0402]  127.29 57.04 90 bottom
RD27  24.9_0402_1%  [R_0402]  144.66 57.04 90 bottom
RD28  24.9_0402_1%  [R_0402]  124.24 57.04 90 bottom
RD29  34.8_0402_1%  [R_0402]  168.13 53.43 180 bottom
RD30  34.8_0402_1%  [R_0402]  106.26 53.94 0 bottom
RD31  34.8_0402_1%  [R_0402]  168.13 52.42 180 bottom
RD32  34.8_0402_1%  [R_0402]  107.53 52.04 0 bottom
RD33  34.8_0402_1%  [R_0402]  165.59 52.67 180 bottom
RD34  34.8_0402_1%  [R_0402]  106.26 53.05 0 bottom
RD35  34.8_0402_1%  [R_0402]  168.18 46.12 90 bottom
RD36  34.8_0402_1%  [R_0402]  106.26 46.07 0 bottom
RD37  34.8_0402_1%  [R_0402]  165.59 54.96 180 bottom
RD38  34.8_0402_1%  [R_0402]  107.43 57.35 180 bottom
RD39  34.8_0402_1%  [R_0402]  168.13 55.47 180 bottom
RD40  34.8_0402_1%  [R_0402]  108.95 55.97 180 bottom
RD41  34.8_0402_1%  [R_0402]  165.59 55.97 180 bottom
RD42  34.8_0402_1%  [R_0402]  108.95 54.96 180 bottom
RD43  34.8_0402_1%  [R_0402]  168.13 56.48 180 bottom
RD44  34.8_0402_1%  [R_0402]  106.26 54.96 0 bottom
RD45  34.8_0402_1%  [R_0402]  167.22 51.4 0 bottom
RD46  34.8_0402_1%  [R_0402]  110.32 58.26 0 bottom
RD47  34.8_0402_1%  [R_0402]  166.56 58.11 0 bottom
RD48  34.8_0402_1%  [R_0402]  105.98 56.35 0 bottom
RD49  34.8_0402_1%  [R_0402]  169.51 57.24 0 bottom
RD50  34.8_0402_1%  [R_0402]  105.07 57.96 270 bottom
RD51  34.8_0402_1%  [R_0402]  168.13 54.45 180 bottom
RD52  34.8_0402_1%  [R_0402]  112.3 57.04 90 bottom
RD53  34.8_0402_1%  [R_0402]  169.51 58.26 0 bottom
RD54  34.8_0402_1%  [R_0402]  107.81 51.15 0 bottom
RD55  34.8_0402_1%  [R_0402]  165.59 53.69 180 bottom
RD56  34.8_0402_1%  [R_0402]  110.32 56.99 0 bottom
RD57  34.8_0402_1%  [R_0402]  164.37 57.96 270 bottom
RD58  34.8_0402_1%  [R_0402]  108.27 58.26 180 bottom
RD59  34.8_0402_1%  [R_0402]  165.64 57.96 270 bottom
RD60  34.8_0402_1%  [R_0402]  108.95 53.94 180 bottom
RD61  34.8_0402_1%  [R_0402]  168.13 49.12 180 bottom
RD62  34.8_0402_1%  [R_0402]  109.21 47.85 180 bottom
RD63  34.8_0402_1%  [R_0402]  164.68 42.77 0 bottom
RD64  34.8_0402_1%  [R_0402]  106.26 47.85 0 bottom
RD65  34.8_0402_1%  [R_0402]  164.68 48.1 0 bottom
RD66  34.8_0402_1%  [R_0402]  106.26 44.16 0 bottom
RD67  34.8_0402_1%  [R_0402]  164.68 41.75 0 bottom
RD68  34.8_0402_1%  [R_0402]  106.26 43.27 0 bottom
RD69  34.8_0402_1%  [R_0402]  164.68 47.08 0 bottom
RD70  34.8_0402_1%  [R_0402]  106.08 51.86 270 bottom
RD71  34.8_0402_1%  [R_0402]  164.68 50.13 0 bottom
RD72  34.8_0402_1%  [R_0402]  109.21 49.88 180 bottom
RD73  34.8_0402_1%  [R_0402]  167.22 50.39 0 bottom
RD74  34.8_0402_1%  [R_0402]  106.97 50.59 270 bottom
RD75  34.8_0402_1%  [R_0402]  164.68 51.15 0 bottom
RD76  34.8_0402_1%  [R_0402]  106.26 46.96 0 bottom
RD77  34.8_0402_1%  [R_0402]  168.13 48.1 180 bottom
RD78  34.8_0402_1%  [R_0402]  109.21 46.96 180 bottom
RD79  34.8_0402_1%  [R_0402]  164.68 49.12 0 bottom
RD80  34.8_0402_1%  [R_0402]  105.98 48.73 0 bottom
RD81  30_0402_1%  [R_0402]  183.93 57.04 90 bottom
RD82  30_0402_1%  [R_0402]  109.21 48.86 180 bottom
RD83  26.1_0402_1%  [R_0402]  166.28 44.19 180 bottom
RD84  26.1_0402_1%  [R_0402]  109.21 45.05 180 bottom
RD85  26.1_0402_1%  [R_0402]  166.28 45.2 180 bottom
RD86  26.1_0402_1%  [R_0402]  109.21 46.07 180 bottom
RH1  100K_0402_5%  [R_0402]  154.47 2.94 90 bottom
RH2  100K_0402_5%  [R_0402]  155.48 2.94 90 bottom
RH3  1M_0402_5%  [R_0402]  98.64 20.16 0 bottom
RH4  1M_0402_5%  [R_0402]  95.84 11.52 0 bottom
RH11  10K_0402_5%  [R_0402]  120.13 10.63 180 bottom
RH12  10K_0402_5%  [R_0402]  95.84 12.54 0 bottom
RH14  10M_0402_5%  [R_0402]  124.24 25.27 90 bottom
RH15  1M_0402_5%  [R_0402]  107.02 26.26 0 bottom
RH16  10K_0402_5%  [R_0402]  113.27 11.61 180 bottom
RH17  100K_0402_5%  [R_0402]  94.17 17.26 180 bottom
RH18  20K_0402_5%  [R_0402]  122.26 23.21 0 bottom
RH19  20K_0402_5%  [R_0402]  107.02 23.21 0 bottom
RH20  3K_0402_1%  [R_0402]  129.63 7 270 bottom
RH21  10K_0402_5%  [R_0402]  114.84 13.23 0 bottom
RH23  330K_0402_5%  [R_0402]  105.65 27.27 180 bottom
RH24  330K_0402_5%  [R_0402]  105.65 26.26 180 bottom
RH25  1K_0402_5%  [R_0402]  117.69 23.97 0 bottom
RH26  10K_0402_5%  [R_0402]  122.41 9.49 180 bottom
RH27  1M_0402_5%  [R_0402]  120.56 4.59 270 bottom
RH28  51_0402_5%  [R_0402]  161.53 23.45 180 bottom
RH29  10K_0402_5%  [R_0402]  113.96 15.21 0 bottom
RH31  3K_0402_1%  [R_0402]  124.45 6.44 180 bottom
RH32  51_0402_5%  [R_0402]  196.36 9.7 270 bottom
RH33  51_0402_5%  [R_0402]  161.53 27.51 180 bottom
RH34  10K_0402_5%  [R_0402]  95.01 13.61 90 bottom
RH36  1K_0402_5%  [R_0402]  161.53 26.49 180 bottom
RH37  10K_0402_5%  [R_0402]  94.07 12.54 0 bottom
RH38  22_0402_5%  [R_0402]  110.48 18.64 180 bottom
RH39  51_0402_5%  [R_0402]  161.53 25.48 180 bottom
RH40  0_0402_5%  [R0402_0OHM]  94.09 15.44 0 bottom
RH41  22_0402_5%  [R_0402]  112.76 21.07 180 bottom
RH42  10K_0402_5%  [R_0402]  123.53 8.48 0 bottom
RH43  0_0402_5%  [R0402_0OHM]  123.53 7.46 0 bottom
RH44  10K_0402_5%  [R_0402]  108.29 11.78 0 bottom
RH45  0_0402_5%  [R0402_0OHM]  108.29 12.79 0 bottom
RH46  33_0402_5%  [R_0402]  226.86 12.59 90 bottom
RH47  1K_0402_5%  [R_0402]  217 10.51 0 bottom
RH48  1K_0402_5%  [R_0402]  208.87 10.51 0 bottom
RH52  33_0402_5%  [R_0402]  229.02 12.59 90 bottom
RH54  0_0402_5%  [R_0402]  103.72 19.4 0 bottom
RH55  0_0402_5%  [R0402_0OHM]  101.69 17.87 0 bottom
RH56  0_0402_5%  [R0402_0OHM]  101.71 16.96 0 bottom
RH57  0_0402_5%  [R_0402]  106.41 19.4 180 bottom
RH58  1K_0402_5%  [R_0402]  105.65 14.6 180 bottom
RH59  8.2K_0402_5%  [R_0402]  121.5 8.48 0 bottom
RH61  0_0402_5%  [R0402_0OHM]  101.69 13.81 0 bottom
RH62  0_0402_5%  [R_0402]  102.65 15.79 270 bottom
RH63  0_0402_5%  [R0402_0OHM]  99.15 12.03 0 bottom
RH64  100K_0402_5%  [R_0402]  105.65 25.24 180 bottom
RH65  0_0402_5%  [R_0402]  117.05 21.56 0 bottom
RH67  0_0402_5%  [R0402_0OHM]  117.64 22.57 0 bottom
RH68  0_0402_5%  [R0402_0OHM]  101.64 15.79 270 bottom
RH69  0_0402_5%  [R0402_0OHM]  111.85 21.94 0 bottom
RH70  0_0402_5%  [R0402_0OHM]  108.24 28.24 270 bottom
RH71  0_0402_5%  [R0402_0OHM]  101.71 12.92 0 bottom
RH72  0_0402_5%  [R_0402]  107.02 25.24 0 bottom
RH73  0_0402_5%  [R_0402]  115.3 14.29 180 bottom
RH74  0_0402_5%  [R0402_0OHM]  105.65 24.22 180 bottom
RH78  0_0402_5%  [R_0402]  95.84 16.35 0 bottom
RH79  330K_0402_5%  [R_0402]  111.85 19.65 0 bottom
RH80  1M_0402_5%  [R_0402]  107.35 27.32 90 bottom
RH81  330K_0402_5%  [R_0402]  111.85 18.64 0 bottom
RH83  0_0402_5%  [R0402_0OHM]  105.65 15.46 180 bottom
RH89  100K_0402_5%  [R_0402]  94.98 16.35 180 bottom
RH92  10K_0402_5%  [R_0402]  95.84 17.37 0 bottom
RH93  0_0402_5%  [R0402_0OHM]  99.55 16.1 180 bottom
RH94  100K_0402_5%  [R_0402]  112.24 9.62 90 bottom
RH95  8.2K_0402_5%  [R_0402]  117.64 11.83 90 bottom
RH96  10K_0402_5%  [R_0402]  115.56 12.03 180 bottom
RH99  100K_0402_5%  [R_0402]  120.18 12.74 270 bottom
RH100  1K_0402_5%  [R_0402]  92.19 18.13 180 bottom
RH101  100K_0402_5%  [R_0402]  118.35 10.63 180 bottom
RH102  SHORT PADS  [SHORTPADS]  118.91 12.29 90 bottom
RH103  SHORT PADS  [SHORTPADS]  117.89 9.49 180 bottom
RH105  1K_0402_5%  [R_0402]  116.62 11.83 90 bottom
RH107  10K_0402_5%  [R_0402]  107.53 17.62 0 bottom
RH109  10K_0402_5%  [R_0402]  103.11 26.26 180 bottom
RH110  10K_0402_5%  [R_0402]  95.08 23.21 0 bottom
RH111  10K_0402_5%  [R_0402]  120.48 22.19 0 bottom
RH112  1K_0402_5%  [R_0402]  122.21 11.47 270 bottom
RH113  1K_0402_5%  [R_0402]  120.61 9.42 270 bottom
RH114  100K_0402_5%  [R_0402]  126.4 5.5 90 bottom
RH119  100K_0402_5%  [R_0402]  111.21 10.81 180 bottom
RH120  10K_0402_5%  [R_0402]  114.39 17.21 180 bottom
RH121  10K_0402_5%  [R_0402]  113.47 16.35 0 bottom
RH122  10K_0402_5%  [R_0402]  102.86 20.16 180 bottom
RH123  10K_0402_5%  [R_0402]  101.94 21.18 0 bottom
RH124  10K_0402_5%  [R_0402]  111.24 11.78 180 bottom
RH125  10K_0402_5%  [R_0402]  110.32 12.79 0 bottom
RH126  1K_0402_5%  [R_0402]  123.53 9.49 0 bottom
RH129  10K_0402_5%  [R_0402]  95.08 21.18 0 bottom
RH132  100K_0402_5%  [R_0402]  96 22.19 180 bottom
RH133  22.6_0402_1%  [R_0402]  121.4 23.08 180 bottom
RH134  3K_0402_1%  [R_0402]  125.49 6.12 90 bottom
RH135  0_0603_5%  [R0603_0OHM]  109.32 27.65 0 bottom
RH136  0_0402_5%  [R0402_0OHM]  114.13 22.95 0 bottom
RH137  0_0402_5%  [R0402_0OHM]  115.05 27.02 180 bottom
RH138  0_0402_5%  [R_0402]  103.11 28.29 180 bottom
RH139  0_0402_5%  [R_0402]  99.91 10 0 bottom
RH140  0_0402_5%  [R0402_0OHM]  121.19 11.47 270 bottom
RH141  0_0402_5%  [R_0402]  114.13 23.97 0 bottom
RH142  0_0402_5%  [R_0402]  123.23 11.47 270 bottom
RH143  0_0402_5%  [R0402_0OHM]  100.16 25.24 0 bottom
RH144  0_0402_5%  [R0402_0OHM]  110.48 23.21 180 bottom
RH145  0_0603_5%  [R_0603]  134.15 31.76 270 bottom
RH146  0_0603_5%  [R0603_0OHM]  135.61 29.03 180 bottom
RH147  0_0402_5%  [R0402_0OHM]  110.48 24.22 180 bottom
RH148  0_0402_5%  [R_0402]  198.16 4.36 270 bottom
RH152  0_0402_5%  [R_0402]  196.12 4.36 270 bottom
RH153  0_0402_5%  [R_0402]  197.14 4.36 270 bottom
RH154  0_0402_5%  [R_0402]  199.17 4.36 270 bottom
RH155  0_0402_5%  [R_0402]  194.6 5.99 90 bottom
RH156  0_0402_5%  [R_0402]  195.62 5.99 90 bottom
RH157  0_0402_5%  [R_0402]  195.39 8.81 90 bottom
RH158  0_0402_5%  [R_0402]  194.35 8.81 90 bottom
RH159  51_0402_5%  [R_0402]  193.58 5.99 90 bottom
RH160  1K_0402_5%  [R_0402]  193.46 8.81 90 bottom
RH161  0_0402_5%  [R_0402]  190.41 9.72 270 bottom
RH163  0_0402_5%  [R_0402]  192.01 4.41 180 bottom
RH164  1K_0402_5%  [R_0402]  191.43 8.81 90 bottom
RH166  2.2K_0402_5%  [R_0402]  304.33 90.82 90 bottom
RH167  2.2K_0402_5%  [R_0402]  305.34 90.82 90 bottom
RH168  10K_0402_5%  [R_0402]  107.22 11.98 270 bottom
RH169  100K_0402_5%  [R_0402]  95.92 14.52 270 bottom
RH170  10K_0402_5%  [R_0402]  114.29 29.81 180 bottom
RH171  10K_0402_5%  [R_0402]  101.08 26.26 180 bottom
RH172  10K_0402_5%  [R_0402]  113.02 26.13 180 bottom
RH173  10K_0402_5%  [R_0402]  113.02 25.24 180 bottom
RH174  100K_0402_5%  [R_0402]  127.26 6.42 270 bottom
RH175  10K_0402_5%  [R_0402]  119.59 22.12 90 bottom
RH176  10K_0402_5%  [R_0402]  122.69 7.46 180 bottom
RH177  100K_0402_5%  [R_0402]  116.83 8.09 180 bottom
RH178  100K_0402_5%  [R_0402]  114.13 8.09 0 bottom
RH179  0_0402_5%  [R_0402]  119.71 21.26 180 bottom
RP1  10K_8P4R_5%  [RP_0804_8P4R]  115.85 9.42 90 bottom
RP2  33_8P4R_5%  [RP_0804_8P4R]  104.87 28.55 0 bottom
RP4  33_0804_8P4R_5%  [RP_0804_8P4R]  225.07 13.73 90 bottom
RP5  1K_0804_8P4R_1%  [RP_0804_8P4R]  99.93 18.88 180 bottom
RP6  33_0804_8P4R_5%  [RP_0804_8P4R]  226.43 15.91 270 bottom
RP7  10K_8P4R_5%  [RP_0804_8P4R]  104.19 17.94 270 bottom
RP8  10K_8P4R_5%  [RP_0804_8P4R]  99.03 13.31 0 bottom
RP9  10K_8P4R_5%  [RP_0804_8P4R]  111.61 16.34 180 bottom
RP11  33_8P4R_5%  [RP_0804_8P4R]  213.15 11.59 270 bottom
RP12  100K_0804_8P4R_5%  [RP_0804_8P4R]  291.13 73.82 270 bottom
RP13  100K_0804_8P4R_5%  [RP_0804_8P4R]  294.43 90.08 270 bottom
RP14  2.2K_0804_8P4R_5%  [RP_0804_8P4R]  288.06 89.43 90 bottom
RP15  2.2K_0804_8P4R_5%  [RP_0804_8P4R]  292.63 88.93 90 bottom
RP16  10K_8P4R_5%  [RP_0804_8P4R]  279.37 85.07 0 bottom
RP17  10K_8P4R_5%  [RP_0804_8P4R]  294.43 93 270 bottom
RP19  2.2K_0804_8P4R_5%  [RP_0804_8P4R]  150.92 6.26 270 bottom
RP20  100K_0804_8P4R_5%  [RP_0804_8P4R]  288.31 72.67 90 bottom
RP21  100K_0804_8P4R_5%  [RP_0804_8P4R]  279.37 82.15 0 bottom
RP22  1K_0804_8P4R_1%  [RP_0804_8P4R]  104.59 11.59 270 bottom
RP23  1K_0804_8P4R_1%  [RP_0804_8P4R]  107.41 14.84 0 bottom
RP24  100K_0804_8P4R_5%  [RP_0804_8P4R]  114.02 20.17 0 bottom
RTCD1  -  [BAT54HT1G_SOD323-2]  290.46 13.26 180 bottom
RTCR1  1K_0402_5%  [R_0402]  291.82 13.25 270 bottom
RV1  100K_0402_5%  [R_0402]  22.13 31.89 90 bottom
RZ3  1M_0402_5%  [R_0402]  287.82 46.12 90 bottom
RZ4  10K_0402_5%  [R_0402]  280.64 50.09 0 bottom
RZ5  10K_0402_5%  [R_0402]  283.3 50.09 180 bottom
SW6  NTC033-XK1K-A160T_4P  [SW_NTC033-XK1K-A160T_4P]  299.76 70.6 180 bottom
T1  PAD~D  [TPC12]  125.87 19.97 180 bottom
T2  PAD~D  [TPC12]  166.84 13.74 180 bottom
T3  PAD~D  [TPC12]  165.66 14.27 180 bottom
T4  PAD~D  [TPC12]  164.25 13.78 180 bottom
T5  PAD~D  [TPC12]  163.41 13.78 180 bottom
T6  PAD~D  [TPC12]  159.41 12.13 180 bottom
T7  PAD~D  [TPC12]  163.71 14.19 180 bottom
T8  PAD~D  [TPC12]  163.23 15.37 180 bottom
T9  PAD~D  [TPC12]  164.53 10.89 180 bottom
T10  PAD~D  [TPC12]  165.92 10.46 180 bottom
T11  PAD~D  [TPC12]  168.24 5.49 180 bottom
T12  PAD~D  [TPC12]  159.62 10.73 180 bottom
T13  PAD~D  [TPC12]  167.96 6.95 180 bottom
T14  PAD~D  [TPC12]  167.92 10.51 180 bottom
T15  PAD~D  [TPC12]  169.47 8.1 180 bottom
T16  PAD~D  [TPC12]  159.69 26.23 180 bottom
T17  PAD~D  [TPC12]  160.93 24.49 180 bottom
T18  PAD~D  [TPC12]  159.69 27.53 180 bottom
T19  PAD~D  [TPC12]  159.66 24.94 180 bottom
T20  PAD~D  [TPC12]  159.38 23.68 180 bottom
T21  PAD~D  [TPC12]  107.96 13.71 180 bottom
T22  PAD~D  [TPC12]  95.92 15.42 180 bottom
T23  PAD~D  [TPC12]  120.75 13.62 180 bottom
T24  PAD~D  [TPC12]  94.85 17.26 180 bottom
T35  PAD~D  [TPC12]  110.53 13.73 180 bottom
T36  PAD~D  [TPC12]  112.77 12.83 180 bottom
T37  PAD~D  [TPC12]  113 15.46 180 bottom
T38  PAD~D  [TPC12]  113.24 14.2 180 bottom
T39  PAD~D  [TPC12]  158.31 15.82 180 bottom
T40  PAD~D  [TPC12]  56.42 18.08 0 top
T41  PAD~D  [TPC12]  126.2 7.16 180 bottom
T42  PAD~D  [TPC12]  126.81 7.16 180 bottom
T43  PAD~D  [TPC12]  126.4 28.3 180 bottom
T44  PAD~D  [TPC12]  127.46 7.16 180 bottom
T45  PAD~D  [TPC12]  125.69 29.41 180 bottom
T46  PAD~D  [TPC12]  125.83 21.53 180 bottom
T47  PAD~D  [TPC12]  293.25 68.86 180 bottom
T48  PAD~D  [TPC12]  168.14 4.09 180 bottom
T49  PAD~D  [TPC12]  103.32 15.16 180 bottom
T50  PAD~D  [TPC12]  100.75 16.26 180 bottom
T51  PAD~D  [TPC12]  19.81 48.01 180 bottom
U1  -  [W25Q64FVSSIQ_SO8]  223.48 3.88 180 bottom
U2  -  [W25Q64FVSSIQ_SO8]  235.37 3.65 180 bottom
U4  -  [74CBTLV3126DS_SSOP16]  171.8 8.86 0 bottom
U5  -  [SN74AHC1G08DCKR_SC70-5]  179.25 4.15 180 bottom
U6  -  [APL3512ABI-TRG_SOT23-5]  251.24 18.35 180 bottom
U7  SN74AUP1G04DCKR_SOT23-5  [SN74AHC1G04DCKR_SOT23-5]  239.48 3.51 90 bottom
U21  -  [AT97SC3205_TSSOP28]  226.44 24.84 0 bottom
U24  -  [APE8937GN2_DFN8_2X2]  239.14 18.52 90 bottom
U25  APE8990GN3B_SON14_2X3  [TPS22966DPUR_SON14_2X3]  228.12 28.74 90 bottom
U26  APE8990GN3B_SON14_2X3  [TPS22966DPUR_SON14_2X3]  76.75 48.54 270 bottom
U27  APE8990GN3B_SON14_2X3  [TPS22966DPUR_SON14_2X3]  299.81 59.65 180 bottom
U28  -  [NCP4545IMNTWG_QFN18_3X3]  87.16 35.24 270 bottom
U29  APE8990GN3B_SON14_2X3  [TPS22966DPUR_SON14_2X3]  34.51 40.98 180 bottom
U30  APE8990GN3B_SON14_2X3  [TPS22966DPUR_SON14_2X3]  11.2 40.04 90 bottom
U33  APE8990GN3B_SON14_2X3  [TPS22966DPUR_SON14_2X3]  11.2 36.49 90 bottom
U34  -  [APE8937GN2_DFN8_2X2]  297.39 52.25 0 bottom
U37  -  [74AUP1G07GW_TSSOP5]  186.59 3.51 90 bottom
U38  MEC1641-PZV_TFBGA144  [MEC1641-PZV_TFBGA_144P]  293.61 84.63 180 bottom
U46  -  [APX9136QFI-TRG_VTDFN6_1P6X1P6]  1.8 38.43 0 bottom
U51  -  [SN74AHC1G08DCKR_SC70-5]  5.62 31.45 90 bottom
U53  TXB0104YZTR_DSBGA12  [TXB0104YZTR_DSBGA_12P]  56.67 4.15 180 bottom
U54  -  [SN74AHC1G08DCKR_SC70-5]  300.53 85.43 180 bottom
U56  -  [PS8713BTQFN24GTR2_TQFN24_4X4]  72.73 16.83 0 bottom
U57  -  [APE8937GN2_DFN8_2X2]  80.06 15.16 0 bottom
U58  -  [G601A31U_ADFN6_1P5X1P5]  281.72 90.41 270 bottom
U59  -  [APE8937GN2_DFN8_2X2]  75.31 40.06 90 bottom
U60  -  [SN74AHC1G08DCKR_SC70-5]  301.26 49.95 180 bottom
U61  -  [SN74AHC1G08DCKR_SC70-5]  278.13 53.5 0 bottom
UC1  -  [74AUP1G07GW_TSSOP5]  148.77 31.19 180 bottom
UCPU1  BDW_Y_DDR3L_BGA1234  [BDW-Y-LPDDR3_BGA_1234P-T]  127.63 25.37 90 bottom
UD1  MT41K256M16HA-125M:E_FBGA96  [MT41J256M16RE-15E-D_FBGA_96P]  171.65 42.5 0 bottom
UD2  MT41K256M16HA-125M:E_FBGA96  [MT41J256M16RE-15E-D_FBGA_96P]  184.26 42.5 0 bottom
UD3  MT41K256M16HA-125M:E_FBGA96  [MT41J256M16RE-15E-D_FBGA_96P]  142.32 42.5 0 bottom
UD4  MT41K256M16HA-125M:E_FBGA96  [MT41J256M16RE-15E-D_FBGA_96P]  154.93 42.5 0 bottom
UD5  MT41K256M16HA-125M:E_FBGA96  [MT41J256M16RE-15E-D_FBGA_96P]  125.62 42.5 0 bottom
UD6  MT41K256M16HA-125M:E_FBGA96  [MT41J256M16RE-15E-D_FBGA_96P]  113.01 42.5 0 bottom
UD7  MT41K256M16HA-125M:E_FBGA96  [MT41J256M16RE-15E-D_FBGA_96P]  83.67 42.5 0 bottom
UD8  MT41K256M16HA-125M:E_FBGA96  [MT41J256M16RE-15E-D_FBGA_96P]  96.28 42.5 0 bottom
UH1  -  [SN74AHC1G08DCKR_SC70-5]  96.56 19.79 270 bottom
Y3  32.768KHZ_12.5PF_9H03200031  [Y_9H03200031_2P]  297.22 87.32 270 bottom
YH1  32.768KHZ_12.5PF_9H03200042  [Y_9H03220008_2P]  119.18 25.76 0 bottom
YH2  24MHZ_12PF_7V24000020  [Y_X3G024000DC1H_4P]  115.9 4.63 0 bottom

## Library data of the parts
C1 C2 C5 C7-C10 C12-C14 C17 C19 C21 C23 C29 C30 C32-C35 C74-C79 C90 C92-C96 C98-C106 C108-C118 C120-C122 C124 C125 C127 C128 C130-C136 C139-C150 C154-C159 C161-C166 C168 C193 C194 C197-C200 C203-C205 C214 C215 C218-C220 C224 C225 C234-C253 C256-C259 C261-C273 CA53-CA57 CC1 CC8-CC11 CD1-CD11 CD14 CD15 CD19-CD29 CD32 CD33 CD36-CD46 CD49 CD50 CD54-CD64 CD67 CD68 CD71-CD80 CD82-CD87 CH1-CH9 CH11 CH15 CH16 CH19 CH21 CH25-CH28 CH30-CH35 CH38-CH42 CH45 CH48 CH49 CH51 CH52 CH54 CH57-CH59 CH61-CH65 CH68 CH69 CH72 CH77-CH90 CH93 CS3 CS4 CS7 CS8 CV1-CV10 CZ2-CZ4 MC1 MC2 MC5 PC1-PC6 PC8 PC10 PC11 PC55 PC56 PC60 PC70 PC80 PC108 PC110 PC303 PC305 PC306 PC314 PC400 PC402 PC404-PC408 PC410 PC412-PC415 PC500 PC503 PC504 PC508 PC519 PC523 PC531 PC533 PC537 PC538 PC540-PC542 PC547 PC549 PC559 PC600 PC601 PC610 PC612-PC614 PC701 PC703 PC704 PC707 PC709 PC715 PC716 PC721 PC723-PC725 PC760 PC814-PC836 PC840 PC900-PC903 PC905 PC906 = C_0402
C4 C6 C11 C16 C18 C20 C22 C31 C97 C107 C119 C123 C126 C129 C160 C255 CC2-CC7 CD12 CD13 CD16 CD17 CD30 CD31 CD34 CD35 CD47 CD48 CD51 CD52 CD65 CD66 CD69 CD70 CD81 CD88 CH20 CH44 CH46 CH47 CH50 CH53 CH55 CH56 CH60 PC300 PC309-PC312 PC403 PC411 PC502 PC505 PC511-PC514 PC532 PC534 PC604 PC607 PC611 PC700 PC702 PC705 PC708 PC718 PC722 PC800-PC813 PC904 PC907 = C_0603
C216 C217 = C_X
C221-C223 CD18 CD53 PC307 PC308 PC609 PC617 = C_B2
C260 = C_D2E
CH66 CH67 CH70 CH71 CH73-CH76 PC313 PC315 PC401 PC409 PC506 PC507 PC509 PC510 PC515 PC517 PC539 PC602 PC603 PC605 PC606 PC706 PC713 PC714 PC717 PC719 PC720 PC726-PC732 = C_0805
CLIP1-CLIP15 CLIP17-CLIP24 = EMIST_SUL-12A2M_1P
CLRP1 CLRP3 R210 RH102 RH103 = SHORTPADS: User Part Number: PART#
D1 D3 D4 D13 D18-D20 = BAT54CW-7-F_SOT323-3
D21 D22 PD1 PD701 = SDMK0340L-7-F_SOD323-2
D23 = ESD207-B1-02EL_TSLP-2-19-2
DA1 DA5 = TVNST52302AB0_SOT523-3
DA8 PD3 PD4 = PJSOT24CW_SOT323-3
FD1-FD4 = FIDUCIAL_C40M80
H1 H4-H6 = H_4P6
H2 = H_4P0X5P0
H3 = H_3P7
H7 = H_4P0N
H8 H9 = H_1P2
JAPS1 = E-T_6705K-Y18N-00L_18P
JAUD1 = ACES_51015-05001-002_50P
JBAT1 = FOX_GS73091-10272M-7H_9P
JBT1 = ACES_50278-00201-001_2P
JCAN1 = ACES_50406-02071-001_20P
JDEBUG JDEG1 JLPDE1 = ACES_50521-01041-P01_10P
JIO1 = HRS_FH29DJ-70S-0P2SHW-05_70P-T
JLVDS1 = ACES_50406-03071-001_30P
JNGFF1 = BELLW_80148-1721_67P-T
JNGFF2 JNGFF3 = BELLW_80149-2021_67P-T
JPWR1 = ACES_50281-00601-001_6P-T
JSNR1 = E-T_6718K-Y24N-20L_24P-T
JSPI1 = ACES_50696-0200M-001_20P-T
JSPK1 = E-T_3703K-F04N-03R_4P
JTS1 = ACES_50521-0084N-P01_8P
JUSH1 = E-T_6705K-Y20N-00L_20P
JXDP1 = E-T_6601K-Y61N-04L_61P
L1-L3 = MURAT_LQM2MPN2R2NG0L_2P
L10 = KC_FBMA-L11-160808-800LMT_2P
L11-L14 = MURAT_BLM15PX181SN1D_2P
LH1 LH2 = MURAT_LQM21PN2R2MC0D_2P
LH3 R19 = R0805_0OHM
MD1 MD2 MD7 MD14 = IP4223CZ6_SO6-6
ML1 ML5 ML6 ML10 = MURAT_DLW21HN900HQ2L_4P
PC111 = C_D2
PD700 = BAT54CW_SOT323-3
PH503 PH504 PR1-PR3 PR5 PR7-PR10 PR12 PR13 PR30 PR40-PR46 PR49 PR55 PR58 PR60-PR63 PR65 PR67 PR70-PR77 PR80 PR81 PR94 PR102-PR106 PR130 PR300-PR306 PR311 PR401 PR403 PR404 PR406 PR408 PR409 PR501 PR504-PR506 PR508-PR510 PR512-PR514 PR518 PR520 PR521 PR526 PR529 PR530 PR540 PR542 PR550 PR562-PR565 PR601 PR604-PR607 PR701 PR702 PR706 PR707 PR709 PR710 PR712 PR718 PR721 PR723 PR740 PR745 PR770-PR774 PR900-PR913 R1 R2 R6-R8 R12-R17 R20 R22 R23 R28 R32 R33 R35 R40 R41 R44 R48 R68 R70 R72 R73 R79 R138 R139 R147 R148 R155 R158 R162 R163 R167-R171 R173-R177 R179-R185 R187-R189 R192 R194 R195 R201 R207 R212 R214 R215 R219 R223 R225 R227-R231 R233-R237 R239 R243 R244 R284 R290 R303 R306 R308-R310 R316-R320 R322 R324 R326-R328 R330-R334 R337-R343 R348-R350 R353 R354 R356 R358 R361-R364 R366-R369 R371 R379-R384 R386-R391 RC1 RC2 RC4 RC6 RC8 RC10-RC19 RC21 RC22 RC24 RC26 RC32-RC37 RC39 RC51 RD1-RD86 RH1-RH4 RH11 RH12 RH14-RH21 RH23-RH29 RH31-RH34 RH36-RH39 RH41 RH42 RH44 RH46-RH48 RH52 RH54 RH57-RH59 RH62 RH64 RH65 RH72 RH73 RH78-RH81 RH89 RH92 RH94-RH96 RH99-RH101 RH105 RH107 RH109-RH114 RH119-RH126 RH129 RH132-RH134 RH138 RH139 RH141 RH142 RH148 RH152-RH161 RH163 RH164 RH166-RH179 RTCR1 RV1 RZ3-RZ5 = R_0402
PJ300 PJ301 PJ600 PJP500 = JUMP_43X118
PJ602 PJP400 PJP401 PJP701 = JUMP_43X39
PL1 PL300 PL304 PL500 PL600 = TAI-T_HCB2012KF-121T50_2P
PL301 PL302 PL601 PL701 = MAG_MMD-06BD-2R2M-X2L_2P
PL400 PL402 = TAI-T_HCB1608KF-121T3_L0603_2P
PL401 PL403 = TOKO_1239AS-H-2R2N-P2_2P
PL501 = MAG_MMD-06BD-1R0M-X2L_2P
PL503 = L_1812-1806
PL504 = MAG_MMD-06BD-R22MEV1L_4P
PL700 = KC_FBMA-L11-201209-121LMA50_2P
PQ1 PQ2 PQ4 PQ5 PQ703 = AON7405_DFN8-5
PQ6 PQ7 PQ30-PQ32 PQ34 PQ51-PQ54 PQ60-PQ62 PQ709 PQ721 = DMN65D8LW-7_SOT323-3
PQ8 PQ720 = SI2303CDS-T1-GE3_SOT23-3
PQ101 = FDV301N_NL_SOT23-3
PQ102 = MMST3904-7-F_SOT323-3
PQ300 PQ501 = CSD87330Q3D_SON8-7
PQ503 PQ600 = AON7934_DFN3X3A8-10
PQ700 = CSD87312Q3E_SON8-4
PQ701 = DCX124EK-7-F_SC74R-6
PQ702 = CSD87351Q5D_SON8-7
PQ900 PQ901 Q1 Q41 Q44 Q45 Q47 QH1 = DMN66D0LDW-7_SOT363-6
PR48 PR56 PR59 PR78 PR79 PR93 PR95 PR330 PR331 PR400 PR405 PR500 PR507 PR511 PR515-PR517 PR519 PR608 PR609 PR703 PR704 PR711 PR713-PR716 PR722 PR730 PR731 R52 R54 R55 R60-R65 R69 R71 R76 R142 R149 R152 R156 R157 R172 R178 R186 R202 R208 R213 R222 R240 R241 R300 R301 R323 R329 R351 R352 R357 R365 R385 RC20 RC23 RC25 RC27-RC31 RC38 RC40-RC47 RC49 RC50 RH40 RH43 RH45 RH55 RH56 RH61 RH63 RH67-RH71 RH74 RH83 RH93 RH136 RH137 RH140 RH143 RH144 RH147 = R0402_0OHM
PR307 PR308 PR503 PR538 PR546 PR600 PR603 PR708 PR720 R25 R335 R336 R346 R360 RH145 = R_0603
PR309 PR310 PR402 PR407 R39 = R_0805
PR502 PR548 PR560 PR561 PR602 PR705 PR719 R9 R154 R344 = R_1206
PR700 PR717 = R_1206_4P-D
PU300 = TPS51285BRUKR_QFN20_3X3
PU400 PU401 = TLV62150RGTR_QFN16_3X3
PU500 = SY8206DQNC_QFN10_3X3
PU600 = G5616ARZ1U_TQFN20_3X3
PU700 = BQ24777RUYR_WQFN28_4X4
PU702 = ISL95813HRZ-T_QFN20_3X4
PU900 PU904 = LM393DMR2G_MICRO8
PU901 PU902 = M74VHC1GT00DFT2G_SC70-5
Q2 = SI3457BDV-T1-E3_TSOP6
Q3-Q5 Q7 Q13 Q14 Q17 Q18 Q21-Q23 Q43 Q46 Q48 = SSM3K7002FU_SC70-3
Q11 Q15 Q19 = SIS412DN-T1-GE3_POWERPAK8-5
Q12 Q16 Q20 = SI1553CDL-T1-GE3_SC70-6
Q24-Q27 Q29 = MMBT3904WH_SOT323-3
QV1 = BSS138-G_SOT23-3
R10 R11 R78 R146 R370 = R1206_0OHM
R143 R151 R153 R159-R161 R190 R191 R193 R206 R291 R292 R307 R321 R345 RH135 RH146 = R0603_0OHM
RP1 RP2 RP4-RP9 RP11-RP17 RP19-RP24 = RP_0804_8P4R
RTCD1 = BAT54HT1G_SOD323-2
SW6 = SW_NTC033-XK1K-A160T_4P
T1-T24 T35-T51 = TPC12
U1 U2 = W25Q64FVSSIQ_SO8
U4 = 74CBTLV3126DS_SSOP16
